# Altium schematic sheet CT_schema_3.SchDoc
size 276 x 169 mm
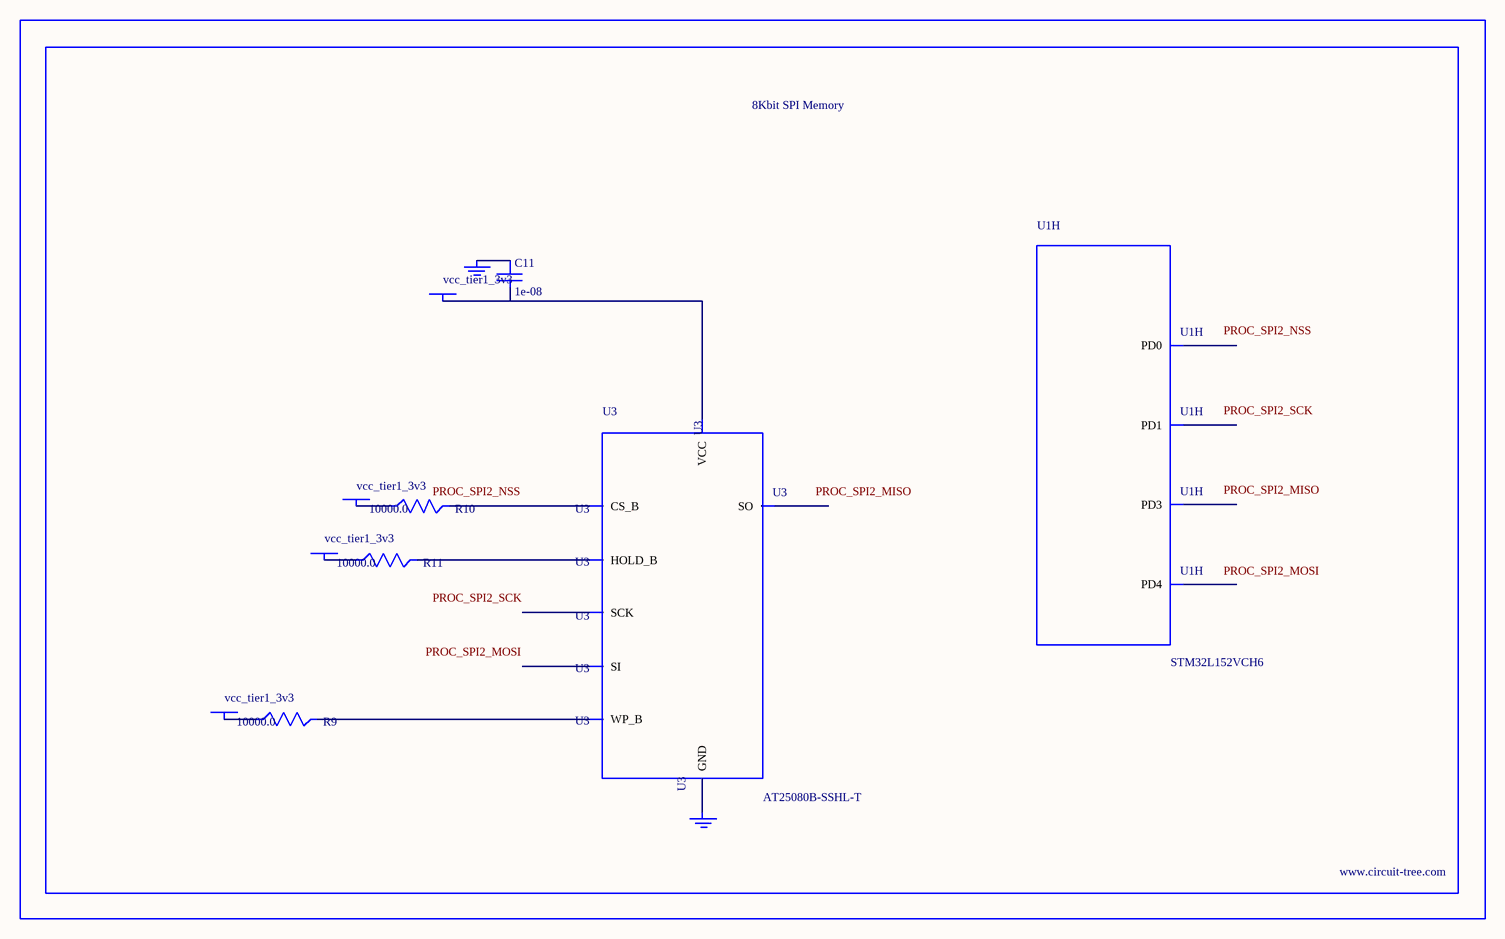
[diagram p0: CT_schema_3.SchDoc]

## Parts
BORDER2  (no value)
C11  1e-08  [C0402]
GND_INSTANCE_2_0  (no value)
GND_INSTANCE_2_1  (no value)
POWER_INSTANCE_2_0  vcc_tier1_3v3
POWER_INSTANCE_2_1  vcc_tier1_3v3
POWER_INSTANCE_2_2  vcc_tier1_3v3
POWER_INSTANCE_2_3  vcc_tier1_3v3
R9  10000.0  [R0603]
R10  10000.0  [R0603]
R11  10000.0  [R0603]
U1  STM32L152VCH6  [UFBGA100]  (part H of 11)
U3  AT25080B-SSHL-T  [SOIC-8]

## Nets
NetC11_1: C11.1 GND_INSTANCE_2_0.0(GND)
NetC11_2: C11.2 POWER_INSTANCE_2_3.0(PWR) U3.8(VCC)
NetGND_INSTANCE_2_1_0: GND_INSTANCE_2_1.0(GND) U3.4(GND)
NetPOWER_INSTANCE_2_0_0: POWER_INSTANCE_2_0.0(PWR) R10.1
NetPOWER_INSTANCE_2_1_0: POWER_INSTANCE_2_1.0(PWR) R9.1
NetPOWER_INSTANCE_2_2_0: POWER_INSTANCE_2_2.0(PWR) R11.1
NetR9_2: R9.2 U3.3(WP_B)
NetR10_2: R10.2 U3.1(CS_B)
NetR11_2: R11.2 U3.7(HOLD_B)

Not connected (* = marked no-connect by the designer): U1 B7(PD4) B8(PD3) B9(PD1) C9(PD0); U3 2(SO) 5(SI) 6(SCK)

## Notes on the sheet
- Labels drawn without touching a wire or pin: PROC_SPI2_MISO, PROC_SPI2_MOSI, PROC_SPI2_NSS, PROC_SPI2_SCK

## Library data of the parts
BORDER2 = BORDER_PAGE2
C11 = C0402C103K3RAC
GND_INSTANCE_2_0 GND_INSTANCE_2_1 = GND
POWER_INSTANCE_2_0-POWER_INSTANCE_2_3 = PWR
R9-R11 = RC0603JR-0710KL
